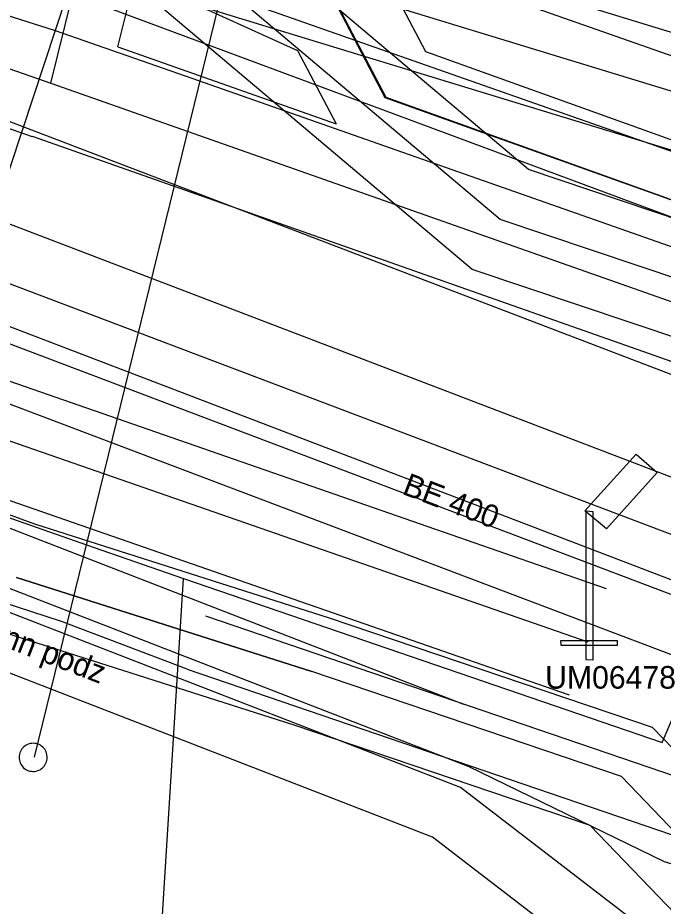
# Model space of a CAD drawing. Extents: x -762993 to -761845, y -975230 to -974501.
# Drawn here: x -762325.37 to -762313.92, y -974991.29 to -974975.53 of the extents above; entities that cross this region are included whole.
import ezdxf

# ---------------------------------------------------------------- set-up
doc = ezdxf.new("R2010")
doc.units = 0
for name, color, linetype in [('IS_CETIN_OP', 7, 'Continuous'), ('IS_CETIN_podzem metalika zam', 7, 'Continuous'), ('IS_CETIN_podzem optika zam', 7, 'Continuous'), ('IS_CETIN_podzem out of order', 7, 'Continuous'), ('IS_CEZ-D_anotace', 7, 'Continuous'), ('IS_CEZ-D_el vedeni NN podzem', 7, 'Continuous'), ('IS_CEZ-D_el vedeni VN podzem', 7, 'Continuous'), ('IS_CEZ-D_OP', 7, 'Continuous'), ('IS_CRA_podzem telekomunikace', 7, 'Continuous'), ('IS_DPmUL_OP', 7, 'Continuous'), ('IS_DPmUL_VO lampy', 7, 'Continuous'), ('IS_DPmUL_VO lampy anotace', 7, 'Continuous'), ('IS_DPmUL_VO vedeni podzem', 7, 'Continuous'), ('IS_GASNET_plyn NTL rad', 7, 'Continuous'), ('IS_GASNET_plyn OP', 7, 'Continuous'), ('IS_SCVK_kanalizace anotace', 7, 'Continuous'), ('IS_SCVK_kanalizace jednotna', 7, 'Continuous'), ('IS_SCVK_kanalizace OP', 7, 'Continuous'), ('IS_SCVK_vodovod OP', 7, 'Continuous'), ('IS_SCVK_vodovod pripojky', 7, 'Continuous'), ('IS_SCVK_vodovod privadec', 7, 'Continuous'), ('IS_SCVK_vodovod znaky', 7, 'Continuous'), ('IS_T-Mobile_OP', 7, 'Continuous'), ('IS_T-Mobile_podzem optika', 7, 'Continuous')]:
    doc.layers.add(name, color=color, linetype=linetype)

msp = doc.modelspace()

# ---------------------------------------------------------------- linework, layer by layer
at = {"layer": 'IS_CETIN_OP'}
for q in [(-762323.322, -974974.951), (-762319.722, -974977.411)]:
    msp.add_line((-762323.592, -974976.048), q, dxfattribs=at)
for points in [[(-762332.038, -974969.868), (-762325.973, -974972.002), (-762323.432, -974972.809), (-762321.256, -974973.527), (-762318.954, -974974.571), (-762318.136, -974976.13), (-762306.451, -974980.321), (-762300.467, -974981.8), (-762292.097, -974984.68), (-762290.767, -974985.008), (-762288.807, -974984.163), (-762287.974, -974982.862), (-762287.982, -974982.827), (-762289.282, -974980.773), (-762286.601, -974981.001), (-762284.415, -974982.166)], [(-762323.322, -974974.951), (-762321.984, -974975.393), (-762320.406, -974976.109), (-762319.722, -974977.411)], [(-762332.021, -974975.214), (-762325.111, -974977.634)], [(-762325.112, -974977.633), (-762299.502, -974986.653)]]:
    msp.add_lwpolyline(points, dxfattribs=at)
at = {"layer": 'IS_CETIN_podzem metalika zam'}
msp.add_lwpolyline([(-762324.78, -974976.69), (-762323.64, -974972.064)], dxfattribs=at)
at = {"layer": 'IS_CETIN_podzem optika zam'}
for points in [[(-762377.62, -974954.57), (-762366.77, -974958.38), (-762363.37, -974959.59), (-762350.74, -974963.98), (-762348.95, -974964.65), (-762339.36, -974968.07), (-762336.01, -974969.53), (-762326.29, -974972.95), (-762323.74, -974973.76), (-762321.62, -974974.46), (-762319.68, -974975.34), (-762318.84, -974976.94), (-762306.74, -974981.28), (-762300.75, -974982.76), (-762292.38, -974985.64), (-762290.68, -974986.06), (-762288.13, -974984.96), (-762286.9, -974983.04), (-762287.05, -974982.43), (-762287.36, -974981.94), (-762286.89, -974981.98), (-762283.27, -974983.91), (-762274.13, -974988.8), (-762260.53, -974993.46)], [(-762331.69, -974974.27), (-762324.78, -974976.69)], [(-762324.78, -974976.69), (-762299.17, -974985.71)]]:
    msp.add_lwpolyline(points, dxfattribs=at)
at = {"layer": 'IS_CETIN_podzem out of order'}
for points in [[(-762393.36, -974970.49), (-762394.76, -974970.05), (-762391.76, -974961.27), (-762386.9, -974962.9), (-762371.15, -974968.61), (-762342.91, -974978.3), (-762324.01, -974984.93), (-762322.43, -974985.48)], [(-762327.23, -974974.06), (-762309.42, -974980.68), (-762296.86, -974985.37), (-762290.2, -974987.41), (-762286.23, -974986.47), (-762283.7, -974985.04), (-762281.71, -974980.9), (-762281.02, -974976.31)], [(-762322.43, -974985.48), (-762313.94, -974988.39), (-762310.47, -974980.29)], [(-762321.6, -974994.35), (-762322.98, -974994.3), (-762322.43, -974985.48)]]:
    msp.add_lwpolyline(points, dxfattribs=at)
at = {"layer": 'IS_CEZ-D_el vedeni NN podzem'}
for points in [[(-762394.922, -974961.348), (-762366.691, -974971.325), (-762338.912, -974980.87), (-762333.235, -974982.66), (-762317.369, -974988.815), (-762313.901, -974990.502), (-762312.492, -974990.931), (-762308.55, -974979.749), (-762308.284, -974978.995), (-762308.259, -974979.004), (-762304.782, -974980.906), (-762293.136, -974984.559), (-762291.208, -974984.727), (-762288.899, -974984.279), (-762285.346, -974981.506), (-762284.881, -974980.325), (-762284.547, -974977.953), (-762290.432, -974954.683), (-762291.314, -974953.684), (-762291.816, -974954.174), (-762292.054, -974954.011)], [(-762342.967, -974959.546), (-762342.778, -974959.612), (-762343.206, -974960.852), (-762344.903, -974966.065), (-762333.585, -974970.475), (-762322.985, -974974.011), (-762312.522, -974977.213), (-762309.333, -974978.189), (-762308.125, -974978.628), (-762304.826, -974980.473), (-762293.058, -974984.165), (-762291.229, -974984.323), (-762289.07, -974983.904), (-762285.678, -974981.258), (-762285.27, -974980.222), (-762284.953, -974977.971), (-762290.8, -974954.871), (-762291.335, -974954.264), (-762291.585, -974954.509), (-762292.054, -974954.011)], [(-762312.434, -975011.429), (-762311.562, -975011.492), (-762311.55, -975011.669), (-762308.991, -975012.245), (-762308.787, -975011.452), (-762307.552, -975006.66), (-762307.854, -974999.844), (-762312.234, -974993.249), (-762317.513, -974989.187), (-762333.367, -974983.038), (-762339.038, -974981.25), (-762354.832, -974975.823), (-762355.035, -974975.753), (-762355.226, -974976.23), (-762356.629, -974979.736), (-762357.615, -974982.215), (-762357.804, -974982.149)]]:
    msp.add_lwpolyline(points, dxfattribs=at)
at = {"layer": 'IS_CEZ-D_el vedeni VN podzem'}
for points in [[(-762322.36, -974987.09), (-762324.59, -974986.24), (-762328.28, -974985.04), (-762360.05, -974973.9), (-762363.79, -974972.56), (-762395.59, -974961.56), (-762398.7, -974960.48), (-762421.28, -974952.57), (-762425.16, -974951.24), (-762434.97, -974947.57)], [(-762322.36, -974987.09), (-762313.05, -974990.27), (-762312.11, -974987.34), (-762310, -974982.03), (-762309.51, -974981.11), (-762307.19, -974981.33), (-762304.87, -974980.04), (-762292.98, -974983.77), (-762291.25, -974983.92), (-762289.24, -974983.53), (-762286.01, -974981.01), (-762285.66, -974980.12), (-762285.36, -974977.99), (-762286.64, -974972.55), (-762286.099, -974971.79), (-762284.398, -974971.517), (-762283.019, -974971.276), (-762271.395, -974968.905), (-762270.582, -974968.65), (-762269.96, -974970.094), (-762269.605, -974971.556), (-762268.637, -974975.689)]]:
    msp.add_lwpolyline(points, dxfattribs=at)
at = {"layer": 'IS_CEZ-D_OP'}
for points in [[(-762425.326, -974953.474), (-762425.823, -974952.392), (-762424.284, -974951.508), (-762423.951, -974951.317), (-762421.468, -974950.868), (-762394.588, -974960.405), (-762366.362, -974970.381), (-762338.599, -974979.92), (-762332.903, -974981.716), (-762317.463, -974987.706)], [(-762343.396, -974958.337), (-762344.154, -974960.534), (-762346.146, -974966.654), (-762333.925, -974971.416), (-762323.29, -974974.964), (-762312.815, -974978.169), (-762309.65, -974979.138), (-762309.424, -974979.22)], [(-762343.396, -974958.337), (-762341.508, -974958.996), (-762342.258, -974961.17), (-762343.66, -974965.476), (-762333.245, -974969.534), (-762322.68, -974973.058), (-762312.229, -974976.257), (-762309.016, -974977.24), (-762307.707, -974977.716), (-762305.235, -974979.099)], [(-762312.622, -975010.413), (-762310.623, -975010.557), (-762310.603, -975010.857), (-762309.718, -975011.056), (-762308.558, -975006.555), (-762308.841, -975000.166), (-762312.975, -974993.94), (-762318.009, -974990.067), (-762333.698, -974983.982), (-762339.351, -974982.2), (-762354.46, -974977.008), (-762355.7, -974980.107), (-762357.04, -974983.475), (-762358.93, -974982.815)], [(-762322.037, -974986.144), (-762313.691, -974988.994), (-762313.052, -974987.002), (-762310.909, -974981.609), (-762310.079, -974980.052), (-762309.729, -974980.085)]]:
    msp.add_lwpolyline(points, dxfattribs=at)
at = {"layer": 'IS_CRA_podzem telekomunikace'}
msp.add_lwpolyline([(-762286.963, -974982.858), (-762286.915, -974983.05), (-762288.133, -974984.967), (-762290.685, -974986.061), (-762292.389, -974985.635), (-762300.689, -974982.775), (-762306.75, -974981.275), (-762318.851, -974976.949), (-762319.685, -974975.352), (-762321.623, -974974.461), (-762323.743, -974973.764), (-762326.285, -974972.953), (-762335.993, -974969.53), (-762339.363, -974968.07), (-762348.947, -974964.652), (-762363.377, -974959.593), (-762377.637, -974954.573), (-762392.217, -974949.493), (-762417.036, -974940.799), (-762419.044, -974939.84), (-762421.242, -974939.701), (-762425.393, -974938.364)], dxfattribs=at)
at = {"layer": 'IS_DPmUL_OP'}
for points in [[(-762342.181, -974976.183), (-762314.929, -974985.655)], [(-762342.837, -974978.073), (-762315.585, -974987.545)]]:
    msp.add_lwpolyline(points, dxfattribs=at)
at = {"layer": 'IS_DPmUL_VO lampy'}
for points in [[(-762314.397, -974983.27), (-762314.027, -974983.6), (-762314.927, -974984.6), (-762315.307, -974984.28)], [(-762315.287, -974984.28), (-762315.167, -974984.29), (-762315.167, -974986.93), (-762315.287, -974986.92)], [(-762315.737, -974986.58), (-762314.737, -974986.58), (-762314.737, -974986.67), (-762315.727, -974986.67)]]:
    msp.add_lwpolyline(points, close=True, dxfattribs=at)
at = {"layer": 'IS_DPmUL_VO vedeni podzem'}
msp.add_lwpolyline([(-762342.509, -974977.128), (-762315.257, -974986.6)], dxfattribs=at)
at = {"layer": 'IS_GASNET_plyn NTL rad'}
msp.add_lwpolyline([(-762416.145, -974949.855), (-762381.041, -974961.735), (-762378.19, -974962.7), (-762377.47, -974962.93), (-762377.29, -974962.99), (-762377.092, -974963.051), (-762377.03, -974963.07), (-762356.37, -974970.3), (-762354.158, -974971.062), (-762353.96, -974971.13), (-762350.61, -974972.23), (-762350.171, -974972.416), (-762350.02, -974972.48), (-762336.17, -974977.35), (-762335.29, -974977.64), (-762335.11, -974977.68), (-762305.627, -974988.849), (-762305.14, -974989.03), (-762304.73, -974989.2), (-762303.75, -974989.6), (-762303.207, -974990.005), (-762302.681, -974990.396), (-762302.34, -974990.65)], dxfattribs=at)
at = {"layer": 'IS_GASNET_plyn OP'}
msp.add_lwpolyline([(-762334.823, -974976.719), (-762305.276, -974987.913), (-762304.774, -974988.099), (-762304.35, -974988.275), (-762303.254, -974988.722), (-762302.61, -974989.203), (-762302.084, -974989.594), (-762301.743, -974989.848), (-762301.411, -974990.095), (-762301.291, -974990.915), (-762301.538, -974991.247), (-762301.785, -974991.579), (-762302.605, -974991.699), (-762302.937, -974991.452), (-762303.278, -974991.198), (-762303.804, -974990.807), (-762304.246, -974990.478), (-762305.11, -974990.125), (-762305.506, -974989.961), (-762305.978, -974989.785), (-762335.397, -974978.641)], dxfattribs=at)
at = {"layer": 'IS_SCVK_kanalizace jednotna'}
msp.add_lwpolyline([(-762330.791, -974977.171), (-762299.318, -974989.209)], dxfattribs=at)
at = {"layer": 'IS_SCVK_kanalizace OP'}
for p, q in [((-762330.184, -974975.583), (-762298.611, -974987.659)), ((-762331.398, -974978.759), (-762300.025, -974990.759))]:
    msp.add_line(p, q, dxfattribs=at)
at = {"layer": 'IS_SCVK_vodovod OP'}
for points in [[(-762370.788, -974956.301), (-762365.679, -974958.103), (-762364.905, -974958.37), (-762350.036, -974963.625), (-762347.061, -974964.615), (-762327.066, -974971.647), (-762323.688, -974972.721), (-762321.219, -974973.584), (-762302.563, -974980.135), (-762292.067, -974983.465), (-762286.179, -974984.538), (-762284.497, -974984.727), (-762283.191, -974984.34)], [(-762371.852, -974959.319), (-762366.733, -974961.125), (-762365.959, -974961.392), (-762351.074, -974966.651), (-762348.097, -974967.643), (-762328.082, -974974.681), (-762324.702, -974975.757), (-762322.277, -974976.604), (-762303.577, -974983.171), (-762292.841, -974986.577), (-762286.645, -974987.706), (-762284.209, -974987.979), (-762282.49, -974987.47)]]:
    msp.add_lwpolyline(points, dxfattribs=at)
at = {"layer": 'IS_SCVK_vodovod pripojky'}
for points in [[(-762324.297, -974974.511), (-762328.705, -974987.869)], [(-762321.798, -974975.275), (-762325.079, -974988.646)]]:
    msp.add_lwpolyline(points, dxfattribs=at)
at = {"layer": 'IS_SCVK_vodovod privadec'}
msp.add_lwpolyline([(-762371.32, -974957.81), (-762366.206, -974959.614), (-762365.432, -974959.881), (-762350.555, -974965.138), (-762347.579, -974966.129), (-762327.574, -974973.164), (-762324.195, -974974.239), (-762321.748, -974975.094), (-762303.07, -974981.653), (-762292.454, -974985.021), (-762286.412, -974986.122), (-762284.353, -974986.353), (-762281.669, -974985.558)], dxfattribs=at)
at = {"layer": 'IS_SCVK_vodovod znaky'}
for points in [[(-762325.216, -974988.435), (-762325.238, -974988.448)], [(-762325.216, -974988.435), (-762325.238, -974988.448)], [(-762325.192, -974988.423), (-762325.216, -974988.435)], [(-762325.192, -974988.423), (-762325.216, -974988.435)], [(-762325.167, -974988.414), (-762325.192, -974988.423)], [(-762325.167, -974988.414), (-762325.192, -974988.423)], [(-762325.142, -974988.407), (-762325.167, -974988.414)], [(-762325.142, -974988.407), (-762325.167, -974988.414)], [(-762325.116, -974988.404), (-762325.142, -974988.407)], [(-762325.116, -974988.404), (-762325.142, -974988.407)], [(-762325.09, -974988.403), (-762325.116, -974988.404)], [(-762325.09, -974988.403), (-762325.116, -974988.404)], [(-762325.063, -974988.405), (-762325.09, -974988.403)], [(-762325.063, -974988.405), (-762325.09, -974988.403)], [(-762325.039, -974988.409), (-762325.063, -974988.405)], [(-762325.039, -974988.409), (-762325.063, -974988.405)], [(-762325.012, -974988.416), (-762325.039, -974988.409)], [(-762325.012, -974988.416), (-762325.039, -974988.409)], [(-762324.988, -974988.426), (-762325.012, -974988.416)], [(-762324.988, -974988.426), (-762325.012, -974988.416)], [(-762324.966, -974988.438), (-762324.988, -974988.426)], [(-762324.966, -974988.438), (-762324.988, -974988.426)], [(-762324.944, -974988.453), (-762324.966, -974988.438)], [(-762324.944, -974988.453), (-762324.966, -974988.438)], [(-762325.338, -974988.597), (-762325.341, -974988.623)], [(-762325.338, -974988.597), (-762325.341, -974988.623)], [(-762325.33, -974988.572), (-762325.338, -974988.597)], [(-762325.33, -974988.572), (-762325.338, -974988.597)], [(-762325.32, -974988.548), (-762325.33, -974988.572)], [(-762325.32, -974988.548), (-762325.33, -974988.572)], [(-762325.308, -974988.525), (-762325.32, -974988.548)], [(-762325.308, -974988.525), (-762325.32, -974988.548)], [(-762325.293, -974988.503), (-762325.308, -974988.525)], [(-762325.293, -974988.503), (-762325.308, -974988.525)], [(-762325.277, -974988.483), (-762325.293, -974988.503)], [(-762325.277, -974988.483), (-762325.293, -974988.503)], [(-762325.258, -974988.464), (-762325.277, -974988.483)], [(-762325.258, -974988.464), (-762325.277, -974988.483)], [(-762325.238, -974988.448), (-762325.258, -974988.464)], [(-762325.238, -974988.448), (-762325.258, -974988.464)], [(-762324.924, -974988.47), (-762324.944, -974988.453)], [(-762324.924, -974988.47), (-762324.944, -974988.453)], [(-762324.905, -974988.489), (-762324.924, -974988.47)], [(-762324.905, -974988.489), (-762324.924, -974988.47)], [(-762324.889, -974988.509), (-762324.905, -974988.489)], [(-762324.889, -974988.509), (-762324.905, -974988.489)], [(-762324.876, -974988.532), (-762324.889, -974988.509)], [(-762324.876, -974988.532), (-762324.889, -974988.509)], [(-762324.864, -974988.555), (-762324.876, -974988.532)], [(-762324.864, -974988.555), (-762324.876, -974988.532)], [(-762324.855, -974988.579), (-762324.864, -974988.555)], [(-762324.855, -974988.579), (-762324.864, -974988.555)], [(-762324.849, -974988.605), (-762324.855, -974988.579)], [(-762324.849, -974988.605), (-762324.855, -974988.579)], [(-762324.845, -974988.631), (-762324.849, -974988.605)], [(-762324.845, -974988.631), (-762324.849, -974988.605)], [(-762325.341, -974988.623), (-762325.344, -974988.649)], [(-762325.341, -974988.623), (-762325.344, -974988.649)], [(-762325.344, -974988.649), (-762325.343, -974988.675)], [(-762325.344, -974988.649), (-762325.343, -974988.675)], [(-762325.343, -974988.675), (-762325.339, -974988.701)], [(-762325.343, -974988.675), (-762325.339, -974988.701)], [(-762325.339, -974988.701), (-762325.332, -974988.726)], [(-762325.339, -974988.701), (-762325.332, -974988.726)], [(-762325.332, -974988.726), (-762325.324, -974988.751)], [(-762325.332, -974988.726), (-762325.324, -974988.751)], [(-762325.324, -974988.751), (-762325.312, -974988.775)], [(-762325.324, -974988.751), (-762325.312, -974988.775)], [(-762324.88, -974988.78), (-762324.867, -974988.758)], [(-762324.88, -974988.78), (-762324.867, -974988.758)], [(-762324.867, -974988.758), (-762324.857, -974988.734)], [(-762324.867, -974988.758), (-762324.857, -974988.734)], [(-762324.857, -974988.734), (-762324.85, -974988.708)], [(-762324.857, -974988.734), (-762324.85, -974988.708)], [(-762324.85, -974988.708), (-762324.845, -974988.682)], [(-762324.85, -974988.708), (-762324.845, -974988.682)], [(-762324.845, -974988.682), (-762324.844, -974988.657)], [(-762324.845, -974988.682), (-762324.844, -974988.657)], [(-762324.844, -974988.657), (-762324.845, -974988.631)], [(-762324.844, -974988.657), (-762324.845, -974988.631)], [(-762325.312, -974988.775), (-762325.297, -974988.797)], [(-762325.312, -974988.775), (-762325.297, -974988.797)], [(-762325.297, -974988.797), (-762325.282, -974988.817)], [(-762325.297, -974988.797), (-762325.282, -974988.817)], [(-762325.282, -974988.817), (-762325.264, -974988.836)], [(-762325.282, -974988.817), (-762325.264, -974988.836)], [(-762325.264, -974988.836), (-762325.244, -974988.853)], [(-762325.264, -974988.836), (-762325.244, -974988.853)], [(-762325.244, -974988.853), (-762325.221, -974988.867)], [(-762325.244, -974988.853), (-762325.221, -974988.867)], [(-762325.221, -974988.867), (-762325.199, -974988.879)], [(-762325.221, -974988.867), (-762325.199, -974988.879)], [(-762325.199, -974988.879), (-762325.175, -974988.889)], [(-762325.199, -974988.879), (-762325.175, -974988.889)], [(-762325.175, -974988.889), (-762325.15, -974988.896)], [(-762325.175, -974988.889), (-762325.15, -974988.896)], [(-762325.15, -974988.896), (-762325.123, -974988.9)], [(-762325.15, -974988.896), (-762325.123, -974988.9)], [(-762325.123, -974988.9), (-762325.097, -974988.903)], [(-762325.123, -974988.9), (-762325.097, -974988.903)], [(-762325.097, -974988.903), (-762325.071, -974988.901)], [(-762325.097, -974988.903), (-762325.071, -974988.901)], [(-762325.071, -974988.901), (-762325.045, -974988.898)], [(-762325.071, -974988.901), (-762325.045, -974988.898)], [(-762325.045, -974988.898), (-762325.02, -974988.892)], [(-762325.045, -974988.898), (-762325.02, -974988.892)], [(-762325.02, -974988.892), (-762324.996, -974988.882)], [(-762325.02, -974988.892), (-762324.996, -974988.882)], [(-762324.996, -974988.882), (-762324.972, -974988.871)], [(-762324.996, -974988.882), (-762324.972, -974988.871)], [(-762324.972, -974988.871), (-762324.95, -974988.857)], [(-762324.972, -974988.871), (-762324.95, -974988.857)], [(-762324.95, -974988.857), (-762324.929, -974988.841)], [(-762324.95, -974988.857), (-762324.929, -974988.841)], [(-762324.929, -974988.841), (-762324.91, -974988.823)], [(-762324.929, -974988.841), (-762324.91, -974988.823)], [(-762324.91, -974988.823), (-762324.894, -974988.802)], [(-762324.91, -974988.823), (-762324.894, -974988.802)], [(-762324.894, -974988.802), (-762324.88, -974988.78)], [(-762324.894, -974988.802), (-762324.88, -974988.78)]]:
    msp.add_lwpolyline(points, dxfattribs=at)
at = {"layer": 'IS_T-Mobile_OP'}
for p, q in [((-762316.311, -974978.223), (-762323.58, -974972.081)), ((-762317.309, -974979.997), (-762324.48, -974973.939)), ((-762307.637, -974981.137), (-762316.311, -974978.223)), ((-762308.063, -974983.103), (-762317.309, -974979.997)), ((-762325.067, -974984.513), (-762335.047, -974980.89)), ((-762319.838, -974986.18), (-762325.067, -974984.513)), ((-762314.107, -974988.121), (-762319.838, -974986.18)), ((-762320.462, -974988.08), (-762325.713, -974986.407)), ((-762315.213, -974989.859), (-762320.462, -974988.08)), ((-762309.913, -974992.497), (-762314.107, -974988.121)), ((-762311.567, -974993.661), (-762315.213, -974989.859))]:
    msp.add_line(p, q, dxfattribs=at)
at = {"layer": 'IS_T-Mobile_podzem optika'}
for points in [[(-762316.81, -974979.11), (-762324.03, -974973.01)], [(-762316.81, -974979.11), (-762324.03, -974973.01)], [(-762307.85, -974982.12), (-762316.81, -974979.11)], [(-762307.85, -974982.12), (-762316.81, -974979.11)], [(-762320.15, -974987.13), (-762325.39, -974985.46)], [(-762325.39, -974985.46), (-762320.15, -974987.13)], [(-762314.66, -974988.99), (-762320.15, -974987.13)], [(-762314.66, -974988.99), (-762320.15, -974987.13)], [(-762310.74, -974993.079), (-762314.66, -974988.99)], [(-762310.74, -974993.079), (-762314.66, -974988.99)]]:
    msp.add_lwpolyline(points, dxfattribs=at)

# ---------------------------------------------------------------- texts
at = {"layer": 'IS_CEZ-D_anotace'}
msp.add_text('Trasa nn podz', height=0.4, rotation=338.8011, dxfattribs=at).set_placement((-762327.09, -974986.116))
at = {"layer": 'IS_DPmUL_VO lampy anotace'}
msp.add_text('UM06478', height=0.4, dxfattribs=at).set_placement((-762316.013, -974987.433))
at = {"layer": 'IS_SCVK_kanalizace anotace'}
msp.add_text('BE 400', height=0.4, rotation=339, dxfattribs=at).set_placement((-762318.566, -974983.973))

doc.saveas('drawing.dxf')
